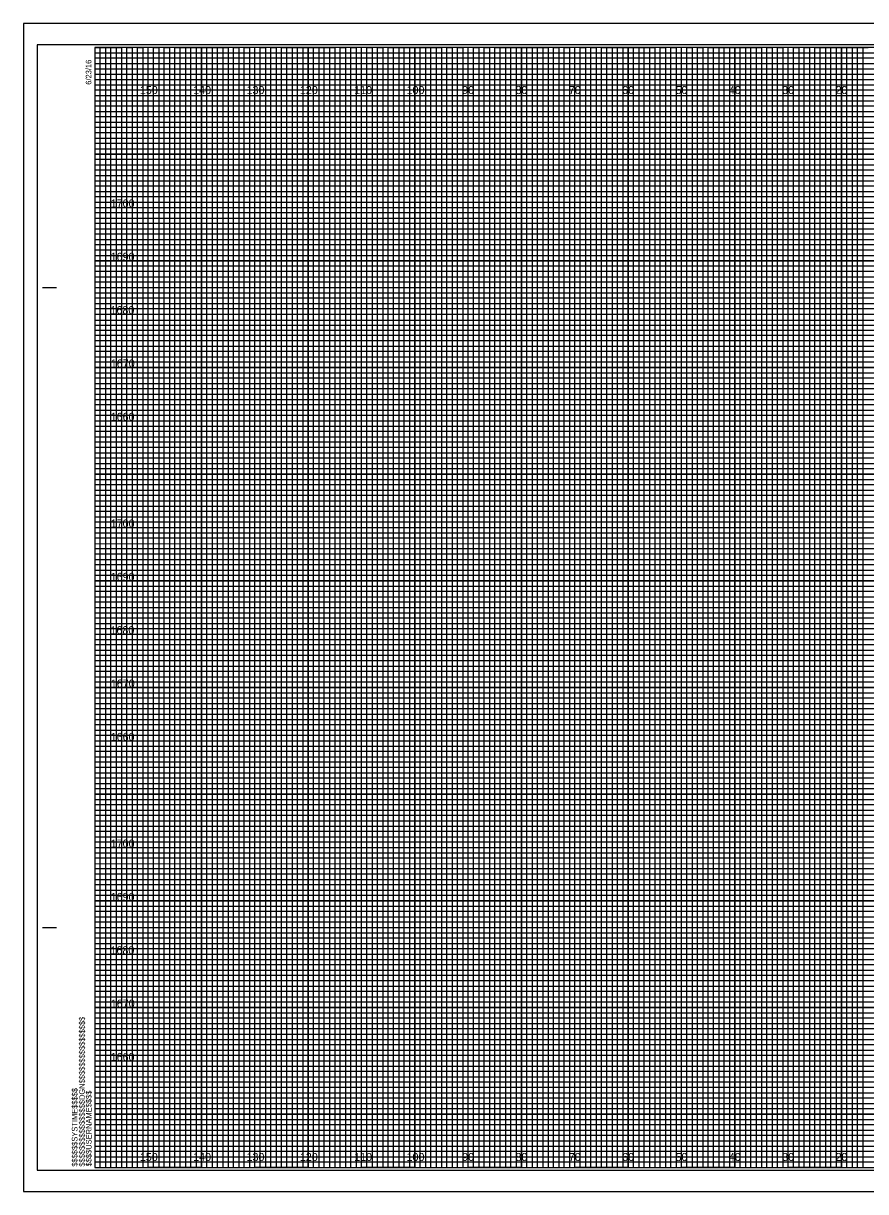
# Model space of a CAD drawing. Extents: x 656 to 993, y -2 to 2857.
# Drawn here: x 656.3 to 814.2, y 1318.3 to 1537.3 of the extents above; entities that cross this region are included whole.
import ezdxf

# ---------------------------------------------------------------- set-up
doc = ezdxf.new("R2010")
doc.units = 0
for name, color, linetype in [('Prop RDY Alternate Text Blue', 7, 'Continuous'), ('Prop Retaining Wall', 7, 'Continuous'), ('Prop SS Cut Line', 7, 'Continuous'), ('Prop SS Fill Line', 7, 'Continuous'), ('Prop SS Transition Line', 7, 'Continuous'), ('Raster_Level_0', 7, 'Continuous'), ('Raster_Level_3', 7, 'Continuous'), ('Scratch_Level_3', 7, 'Continuous'), ('Scratch_Level_7', 7, 'Continuous'), ('Typical Guardrail CELL', 7, 'Continuous'), ('Typical Text Asphalt at Bridge Approach CELL', 7, 'Continuous')]:
    doc.layers.add(name, color=color, linetype=linetype)

msp = doc.modelspace()

# ---------------------------------------------------------------- linework, layer by layer
at = {"layer": 'Prop RDY Alternate Text Blue'}
for p, q in [((679.74, 1322.8), (679.74, 1532.8)), ((689.74, 1322.8), (689.74, 1532.8)), ((699.74, 1322.8), (699.74, 1532.8)), ((709.74, 1322.8), (709.74, 1532.8)), ((719.74, 1322.8), (719.74, 1532.8)), ((729.74, 1322.8), (729.74, 1532.8)), ((739.74, 1322.8), (739.74, 1532.8)), ((749.74, 1322.8), (749.74, 1532.8)), ((759.74, 1322.8), (759.74, 1532.8)), ((769.74, 1322.8), (769.74, 1532.8)), ((779.74, 1322.8), (779.74, 1532.8)), ((789.74, 1322.8), (789.74, 1532.8)), ((799.74, 1322.8), (799.74, 1532.8)), ((809.74, 1322.8), (809.74, 1532.8)), ((669.74, 1522.8), (989.74, 1522.8)), ((669.74, 1512.8), (989.74, 1512.8)), ((669.74, 1502.8), (989.74, 1502.8)), ((669.74, 1492.8), (989.74, 1492.8)), ((669.74, 1482.8), (989.74, 1482.8)), ((669.74, 1472.8), (989.74, 1472.8)), ((669.74, 1462.8), (989.74, 1462.8)), ((669.74, 1452.8), (989.74, 1452.8)), ((669.74, 1442.8), (989.74, 1442.8)), ((669.74, 1432.8), (989.74, 1432.8)), ((669.74, 1422.8), (989.74, 1422.8)), ((669.74, 1412.8), (989.74, 1412.8)), ((669.74, 1402.8), (989.74, 1402.8)), ((669.74, 1392.8), (989.74, 1392.8)), ((669.74, 1382.8), (989.74, 1382.8)), ((669.74, 1372.8), (989.74, 1372.8)), ((669.74, 1362.8), (989.74, 1362.8)), ((669.74, 1352.8), (989.74, 1352.8)), ((669.74, 1342.8), (989.74, 1342.8)), ((669.74, 1332.8), (989.74, 1332.8))]:
    msp.add_line(p, q, dxfattribs=at)
at = {"layer": 'Prop Retaining Wall'}
for p, q in [((659.94, 1487.8), (662.44, 1487.8)), ((660.04, 1487.8), (662.54, 1487.8)), ((659.94, 1367.8), (662.44, 1367.8)), ((660.04, 1367.8), (662.54, 1367.8)), ((669.74, 1322.8), (669.74, 1322.8)), ((669.74, 1322.8), (669.74, 1322.8)), ((669.74, 1322.8), (669.74, 1322.8)), ((669.74, 1322.8), (669.74, 1322.8)), ((669.74, 1322.8), (669.74, 1322.8)), ((669.74, 1322.8), (669.74, 1322.8)), ((669.74, 1322.8), (669.74, 1322.8))]:
    msp.add_line(p, q, dxfattribs=at)
msp.add_lwpolyline([(989.74, 1532.8), (669.74, 1532.8), (669.74, 1322.8), (989.74, 1322.8)], close=True, dxfattribs=at)
at = {"layer": 'Prop SS Cut Line'}
for points in [[(669.74, 1532.8), (674.74, 1532.8), (674.74, 1322.8), (684.74, 1322.8), (684.74, 1532.8), (694.74, 1532.8), (694.74, 1322.8), (704.74, 1322.8), (704.74, 1532.8), (714.74, 1532.8), (714.74, 1322.8), (724.74, 1322.8), (724.74, 1532.8), (734.74, 1532.8), (734.74, 1322.8), (744.74, 1322.8), (744.74, 1532.8), (754.74, 1532.8), (754.74, 1322.8), (764.74, 1322.8), (764.74, 1532.8), (774.74, 1532.8), (774.74, 1322.8), (784.74, 1322.8), (784.74, 1532.8), (794.74, 1532.8), (794.74, 1322.8), (804.74, 1322.8), (804.74, 1532.8), (814.74, 1532.8)], [(669.74, 1527.8), (944.74, 1527.8)], [(669.74, 1507.8), (989.74, 1507.8), (989.74, 1517.8), (669.74, 1517.8)], [(669.74, 1487.8), (989.74, 1487.8), (989.74, 1497.8), (669.74, 1497.8)], [(669.74, 1467.8), (989.74, 1467.8), (989.74, 1477.8), (669.74, 1477.8)], [(669.74, 1447.8), (989.74, 1447.8), (989.74, 1457.8), (669.74, 1457.8)], [(669.74, 1427.8), (989.74, 1427.8), (989.74, 1437.8), (669.74, 1437.8)], [(669.74, 1407.8), (989.74, 1407.8), (989.74, 1417.8), (669.74, 1417.8)], [(669.74, 1387.8), (989.74, 1387.8), (989.74, 1397.8), (669.74, 1397.8)], [(669.74, 1367.8), (989.74, 1367.8), (989.74, 1377.8), (669.74, 1377.8)], [(669.74, 1347.8), (989.74, 1347.8), (989.74, 1357.8), (669.74, 1357.8)], [(669.74, 1327.8), (989.74, 1327.8), (989.74, 1337.8), (669.74, 1337.8)]]:
    msp.add_lwpolyline(points, dxfattribs=at)
at = {"layer": 'Prop SS Fill Line'}
for p, q in [((679.74, 1532.8), (669.74, 1532.8)), ((679.74, 1322.8), (679.74, 1532.8)), ((699.74, 1532.8), (689.74, 1532.8)), ((689.74, 1532.8), (689.74, 1322.8)), ((699.74, 1322.8), (699.74, 1532.8)), ((719.74, 1532.8), (709.74, 1532.8)), ((709.74, 1532.8), (709.74, 1322.8)), ((719.74, 1322.8), (719.74, 1532.8)), ((739.74, 1532.8), (729.74, 1532.8)), ((729.74, 1532.8), (729.74, 1322.8)), ((739.74, 1322.8), (739.74, 1532.8)), ((759.74, 1532.8), (749.74, 1532.8)), ((749.74, 1532.8), (749.74, 1322.8)), ((759.74, 1322.8), (759.74, 1532.8)), ((779.74, 1532.8), (769.74, 1532.8)), ((769.74, 1532.8), (769.74, 1322.8)), ((779.74, 1322.8), (779.74, 1532.8)), ((799.74, 1532.8), (789.74, 1532.8)), ((789.74, 1532.8), (789.74, 1322.8)), ((799.74, 1322.8), (799.74, 1532.8)), ((819.74, 1532.8), (809.74, 1532.8)), ((809.74, 1532.8), (809.74, 1322.8)), ((689.74, 1322.8), (679.74, 1322.8)), ((709.74, 1322.8), (699.74, 1322.8)), ((729.74, 1322.8), (719.74, 1322.8)), ((749.74, 1322.8), (739.74, 1322.8)), ((769.74, 1322.8), (759.74, 1322.8)), ((789.74, 1322.8), (779.74, 1322.8)), ((809.74, 1322.8), (799.74, 1322.8))]:
    msp.add_line(p, q, dxfattribs=at)
for points in [[(669.74, 1522.8), (989.74, 1522.8), (989.74, 1512.8), (669.74, 1512.8)], [(669.74, 1502.8), (989.74, 1502.8), (989.74, 1492.8), (669.74, 1492.8)], [(669.74, 1482.8), (989.74, 1482.8), (989.74, 1472.8), (669.74, 1472.8)], [(669.74, 1462.8), (989.74, 1462.8), (989.74, 1452.8), (669.74, 1452.8)], [(669.74, 1442.8), (989.74, 1442.8), (989.74, 1432.8), (669.74, 1432.8)], [(669.74, 1422.8), (989.74, 1422.8), (989.74, 1412.8), (669.74, 1412.8)], [(669.74, 1402.8), (989.74, 1402.8), (989.74, 1392.8), (669.74, 1392.8)], [(669.74, 1382.8), (989.74, 1382.8), (989.74, 1372.8), (669.74, 1372.8)], [(669.74, 1362.8), (989.74, 1362.8), (989.74, 1352.8), (669.74, 1352.8)], [(669.74, 1342.8), (989.74, 1342.8), (989.74, 1332.8), (669.74, 1332.8)]]:
    msp.add_lwpolyline(points, dxfattribs=at)
at = {"layer": 'Prop SS Transition Line'}
for p, q in [((669.74, 1531.8), (929.74, 1531.8)), ((929.74, 1530.78), (669.74, 1530.78)), ((669.74, 1530.78), (669.74, 1529.8)), ((669.74, 1529.8), (929.74, 1529.8)), ((929.74, 1528.69), (669.74, 1528.69)), ((669.74, 1528.69), (669.74, 1526.8)), ((669.74, 1526.8), (989.74, 1526.8))]:
    msp.add_line(p, q, dxfattribs=at)
for points in [[(669.74, 1525.8), (939.74, 1525.8), (989.74, 1525.8), (989.74, 1524.8), (669.74, 1524.8)], [(669.74, 1523.8), (989.74, 1523.8), (989.74, 1521.8), (669.74, 1521.8)], [(669.74, 1520.8), (989.74, 1520.8), (989.74, 1519.8), (669.74, 1519.78)], [(669.74, 1518.8), (989.74, 1518.8), (989.74, 1516.8), (669.74, 1516.8)], [(669.74, 1515.8), (989.74, 1515.8), (989.74, 1514.8), (669.74, 1514.8)], [(669.74, 1513.8), (989.74, 1513.8), (989.74, 1511.8), (669.74, 1511.8)], [(669.74, 1510.8), (989.74, 1510.8), (989.74, 1509.8), (669.74, 1509.8)], [(669.74, 1508.8), (989.74, 1508.8), (989.74, 1506.8), (669.74, 1506.8)], [(669.74, 1505.8), (989.74, 1505.8), (989.74, 1504.8), (669.74, 1504.8)], [(669.74, 1503.8), (989.74, 1503.8), (989.74, 1501.8), (669.74, 1501.8)], [(669.74, 1500.8), (989.74, 1500.8), (989.74, 1499.8), (669.74, 1499.8)], [(669.74, 1498.8), (989.74, 1498.8), (989.74, 1496.75), (989.74, 1495.8), (989.74, 1494.8), (669.74, 1494.8)], [(669.74, 1496.8), (989.74, 1496.8), (989.74, 1495.8), (669.74, 1495.8)], [(669.74, 1493.8), (989.74, 1493.8), (989.74, 1491.8), (669.74, 1491.83)], [(669.74, 1491.83), (989.74, 1491.8), (989.74, 1490.8), (669.74, 1490.8)], [(669.74, 1489.8), (989.74, 1489.8), (989.74, 1488.8), (669.74, 1488.8)], [(669.74, 1486.8), (989.74, 1486.8), (989.74, 1485.8), (669.74, 1485.8)], [(669.74, 1484.8), (989.74, 1484.8), (989.74, 1483.8), (669.74, 1483.8)], [(669.67, 1481.69), (989.74, 1481.69), (989.74, 1480.68), (669.67, 1480.68)], [(669.74, 1479.8), (989.74, 1479.8), (989.74, 1478.8), (669.74, 1478.8)], [(669.74, 1476.8), (989.74, 1476.8), (989.74, 1475.8), (669.74, 1475.8)], [(669.74, 1474.8), (989.74, 1474.8), (989.74, 1473.8), (669.74, 1473.8)], [(669.74, 1471.8), (989.74, 1471.8), (989.74, 1470.8), (669.74, 1470.8)], [(669.74, 1469.8), (989.74, 1469.8), (989.74, 1468.8), (669.74, 1468.8)], [(669.74, 1466.8), (989.74, 1466.8), (989.74, 1465.8), (669.74, 1465.8)], [(669.74, 1464.8), (989.74, 1464.8), (989.74, 1463.8), (669.74, 1463.8)], [(669.74, 1461.8), (989.74, 1461.8), (989.73, 1460.78), (669.74, 1460.8)], [(669.74, 1459.8), (989.74, 1459.8), (989.74, 1458.8), (669.74, 1458.8)], [(669.74, 1456.8), (989.74, 1456.8), (989.74, 1455.8), (669.74, 1455.8)], [(669.74, 1454.8), (989.74, 1454.8), (989.74, 1453.8), (669.74, 1453.8)], [(669.74, 1451.8), (989.74, 1451.8), (989.74, 1450.8), (669.74, 1450.8)], [(669.74, 1449.8), (989.74, 1449.8), (989.74, 1448.8), (669.74, 1448.8)], [(669.74, 1446.8), (989.74, 1446.8), (989.74, 1445.8), (669.74, 1445.8)], [(669.74, 1444.8), (989.74, 1444.8), (989.74, 1443.8), (669.74, 1443.8)], [(669.74, 1441.8), (989.74, 1441.8), (989.74, 1440.8), (669.74, 1440.8)], [(669.74, 1439.79), (989.81, 1439.71), (989.74, 1438.8), (669.74, 1438.8)], [(669.74, 1436.8), (989.74, 1436.8), (989.74, 1435.8), (669.74, 1435.8)], [(669.74, 1434.8), (989.74, 1434.8), (989.74, 1433.8), (669.74, 1433.8)], [(669.74, 1431.8), (989.74, 1431.8), (989.74, 1430.8), (669.74, 1430.8)], [(669.74, 1429.8), (989.74, 1429.8), (989.74, 1428.8), (669.74, 1428.8)], [(669.74, 1426.8), (989.74, 1426.8), (989.74, 1425.8), (669.74, 1425.8)], [(669.74, 1424.8), (989.74, 1424.8), (989.74, 1423.8), (669.74, 1423.8)], [(669.74, 1421.8), (989.74, 1421.8), (989.74, 1420.8), (669.74, 1420.8)], [(669.74, 1419.8), (989.74, 1419.8), (989.74, 1418.8), (669.74, 1418.8)], [(669.74, 1416.8), (989.74, 1416.8), (989.74, 1415.8), (669.74, 1415.8)], [(669.74, 1414.8), (989.74, 1414.8), (989.74, 1413.8), (669.74, 1413.8)], [(669.74, 1411.8), (989.74, 1411.8), (989.74, 1410.8), (669.74, 1410.8)], [(669.74, 1409.8), (989.74, 1409.8), (989.74, 1408.8), (669.74, 1408.8)], [(669.74, 1406.8), (989.74, 1406.8), (989.74, 1405.8), (669.74, 1405.8)], [(669.74, 1404.8), (989.74, 1404.8), (989.74, 1403.8), (669.74, 1403.8)], [(669.74, 1401.8), (989.74, 1401.8), (989.73, 1400.78), (669.74, 1400.8)], [(669.74, 1399.8), (989.74, 1399.8), (989.74, 1398.8), (669.74, 1398.8)], [(669.74, 1396.8), (989.74, 1396.8), (989.74, 1395.8), (669.74, 1395.8)], [(669.74, 1394.8), (989.74, 1394.8), (989.74, 1393.8), (669.74, 1393.8)], [(669.74, 1391.8), (989.74, 1391.8), (989.74, 1390.8), (669.74, 1390.8)], [(669.74, 1389.8), (989.74, 1389.8), (989.74, 1388.8), (669.74, 1388.8)], [(669.74, 1386.8), (989.74, 1386.8), (989.74, 1385.8), (669.74, 1385.8)], [(669.74, 1384.8), (989.74, 1384.8), (989.74, 1383.8), (669.74, 1383.8)], [(669.74, 1381.8), (989.74, 1381.8), (989.74, 1380.8), (669.74, 1380.8)], [(669.74, 1379.79), (989.81, 1379.71), (989.74, 1378.8), (669.74, 1378.8)], [(669.74, 1376.8), (989.74, 1376.8), (989.74, 1375.8), (669.74, 1375.8)], [(669.74, 1374.8), (989.74, 1374.8), (989.74, 1373.8), (669.74, 1373.8)], [(669.74, 1371.8), (989.74, 1371.8), (989.74, 1370.8), (669.74, 1370.8)], [(669.74, 1369.8), (989.74, 1369.8), (989.74, 1368.8), (669.74, 1368.8)], [(669.74, 1366.8), (989.74, 1366.8), (989.74, 1365.8), (669.74, 1365.8)], [(669.74, 1364.8), (989.74, 1364.8), (989.74, 1363.8), (669.74, 1363.8)], [(669.74, 1361.8), (989.74, 1361.8), (989.74, 1360.8), (669.74, 1360.8)], [(669.74, 1359.8), (989.74, 1359.8), (989.74, 1358.8), (669.74, 1358.8)], [(669.74, 1356.8), (989.74, 1356.8), (989.74, 1355.8), (669.74, 1355.8)], [(669.74, 1354.8), (989.74, 1354.8), (989.74, 1353.8), (669.74, 1353.8)], [(669.74, 1351.8), (989.74, 1351.8), (989.74, 1350.8), (669.74, 1350.8)], [(669.74, 1349.8), (989.74, 1349.8), (989.74, 1348.8), (669.74, 1348.8)], [(669.74, 1346.8), (989.74, 1346.8), (989.74, 1345.8), (669.74, 1345.8)], [(669.74, 1344.8), (989.74, 1344.8), (989.74, 1343.8), (669.74, 1343.8)], [(669.74, 1341.8), (989.74, 1341.8), (989.74, 1340.8), (669.74, 1340.8)], [(669.74, 1339.8), (989.74, 1339.8), (989.74, 1338.8), (669.74, 1338.8)], [(669.74, 1336.8), (989.74, 1336.8), (989.74, 1335.8), (669.74, 1335.8)], [(669.74, 1334.8), (989.74, 1334.8), (989.74, 1333.8), (669.74, 1333.8)], [(669.74, 1331.8), (989.74, 1331.8), (989.74, 1330.8), (669.74, 1330.8)], [(669.74, 1329.8), (989.74, 1329.8), (989.74, 1328.8), (669.74, 1328.8)], [(669.74, 1326.8), (989.74, 1326.8), (989.74, 1325.8), (669.74, 1325.8)], [(669.74, 1324.8), (989.74, 1324.8), (989.74, 1323.8), (669.74, 1323.8)]]:
    msp.add_lwpolyline(points, dxfattribs=at)
at = {"layer": 'Raster_Level_3'}
for points in [[(669.74, 1322.8), (670.74, 1322.8), (670.74, 1532.8), (671.74, 1532.8), (671.74, 1322.8)], [(671.74, 1322.8), (672.74, 1322.8), (672.74, 1532.8), (673.74, 1532.8), (673.74, 1322.8)], [(674.74, 1322.8), (675.74, 1322.8), (675.74, 1532.8), (676.74, 1532.8), (676.74, 1322.8)], [(676.74, 1322.8), (677.74, 1322.8), (677.74, 1532.8), (678.74, 1532.8), (678.74, 1322.8)], [(679.74, 1322.8), (680.74, 1322.8), (680.74, 1532.8), (681.74, 1532.8), (681.74, 1322.8)], [(681.74, 1322.8), (682.74, 1322.8), (682.74, 1532.8), (683.74, 1532.8), (683.74, 1322.8)], [(684.74, 1322.8), (685.74, 1322.8), (685.74, 1532.8), (686.74, 1532.8), (686.74, 1322.8)], [(686.74, 1322.8), (687.74, 1322.8), (687.74, 1532.8), (688.74, 1532.8), (688.74, 1322.8)], [(689.74, 1322.8), (690.74, 1322.8), (690.74, 1532.8), (691.74, 1532.8), (691.74, 1322.8)], [(691.74, 1322.8), (692.74, 1322.8), (692.74, 1532.8), (693.74, 1532.8), (693.74, 1322.8)], [(694.74, 1322.8), (695.74, 1322.8), (695.74, 1532.8), (696.74, 1532.8), (696.74, 1322.8)], [(696.74, 1322.8), (697.74, 1322.8), (697.74, 1532.8), (698.74, 1532.8), (698.74, 1322.8)], [(699.74, 1322.8), (700.74, 1322.8), (700.74, 1532.8), (701.74, 1532.8), (701.74, 1322.8)], [(701.74, 1322.8), (702.74, 1322.8), (702.74, 1532.8), (703.74, 1532.8), (703.74, 1322.8)], [(704.74, 1322.8), (705.74, 1322.8), (705.74, 1532.8), (706.74, 1532.8), (706.74, 1322.8)], [(706.74, 1322.8), (707.74, 1322.8), (707.74, 1532.8), (708.74, 1532.8), (708.74, 1322.8)], [(709.74, 1322.8), (710.74, 1322.8), (710.74, 1532.8), (711.74, 1532.8), (711.74, 1322.8)], [(711.74, 1322.8), (712.74, 1322.8), (712.74, 1532.8), (713.74, 1532.8), (713.74, 1322.8)], [(714.74, 1322.8), (715.74, 1322.8), (715.74, 1532.8), (716.74, 1532.8), (716.74, 1322.8)], [(716.74, 1322.8), (717.74, 1322.8), (717.74, 1532.8), (718.74, 1532.8), (718.74, 1322.8)], [(719.74, 1322.8), (720.74, 1322.8), (720.74, 1532.8), (721.74, 1532.8), (721.74, 1322.8)], [(721.74, 1322.8), (722.74, 1322.8), (722.74, 1532.8), (723.74, 1532.8), (723.74, 1322.8)], [(724.74, 1322.8), (725.74, 1322.8), (725.74, 1532.8), (726.74, 1532.8), (726.74, 1322.8)], [(726.74, 1322.8), (727.74, 1322.8), (727.74, 1532.8), (728.74, 1532.8), (728.74, 1322.8)], [(729.74, 1322.8), (730.74, 1322.8), (730.74, 1532.8), (731.74, 1532.8), (731.74, 1322.8)], [(731.74, 1322.8), (732.74, 1322.8), (732.74, 1532.8), (733.74, 1532.8), (733.74, 1322.8)], [(734.74, 1322.8), (735.74, 1322.8), (735.74, 1532.8), (736.74, 1532.8), (736.74, 1322.8)], [(736.74, 1322.8), (737.74, 1322.8), (737.74, 1532.8), (738.74, 1532.8), (738.74, 1322.8)], [(739.74, 1322.8), (740.74, 1322.8), (740.74, 1532.8), (741.74, 1532.8), (741.74, 1322.8)], [(741.74, 1322.8), (742.74, 1322.8), (742.74, 1532.8), (743.74, 1532.8), (743.74, 1322.8)], [(744.74, 1322.8), (745.74, 1322.8), (745.74, 1532.8), (746.74, 1532.8), (746.74, 1322.8)], [(746.74, 1322.8), (747.74, 1322.8), (747.74, 1532.8), (748.74, 1532.8), (748.74, 1322.8)], [(749.74, 1322.8), (750.74, 1322.8), (750.74, 1532.8), (751.74, 1532.8), (751.74, 1322.8)], [(751.74, 1322.8), (752.74, 1322.8), (752.74, 1532.8), (753.74, 1532.8), (753.74, 1322.8)], [(754.74, 1322.8), (755.74, 1322.8), (755.74, 1532.8), (756.74, 1532.8), (756.74, 1322.8)], [(756.74, 1322.8), (757.74, 1322.8), (757.74, 1532.8), (758.74, 1532.8), (758.74, 1322.8)], [(759.74, 1322.8), (760.74, 1322.8), (760.74, 1532.8), (761.74, 1532.8), (761.74, 1322.8)], [(761.74, 1322.8), (762.74, 1322.8), (762.74, 1532.8), (763.74, 1532.8), (763.74, 1322.8)], [(764.74, 1322.8), (765.74, 1322.8), (765.74, 1532.8), (766.74, 1532.8), (766.74, 1322.8)], [(766.74, 1322.8), (767.74, 1322.8), (767.74, 1532.8), (768.74, 1532.8), (768.74, 1322.8)], [(769.74, 1322.8), (770.74, 1322.8), (770.74, 1532.8), (771.74, 1532.8), (771.74, 1322.8)], [(771.74, 1322.8), (772.74, 1322.8), (772.74, 1532.8), (773.74, 1532.8), (773.74, 1322.8)], [(774.74, 1322.8), (775.74, 1322.8), (775.74, 1532.8), (776.74, 1532.8), (776.74, 1322.8)], [(776.74, 1322.8), (777.74, 1322.8), (777.74, 1532.8), (778.74, 1532.8), (778.74, 1322.8)], [(779.74, 1322.8), (780.74, 1322.8), (780.74, 1532.8), (781.74, 1532.8), (781.74, 1322.8)], [(781.74, 1322.8), (782.74, 1322.8), (782.74, 1532.8), (783.74, 1532.8), (783.74, 1322.8)], [(784.74, 1322.8), (785.74, 1322.8), (785.74, 1532.8), (786.74, 1532.8), (786.74, 1322.8)], [(786.74, 1322.8), (787.74, 1322.8), (787.74, 1532.8), (788.74, 1532.8), (788.74, 1322.8)], [(789.74, 1322.8), (790.74, 1322.8), (790.74, 1532.8), (791.74, 1532.8), (791.74, 1322.8)], [(791.74, 1322.8), (792.74, 1322.8), (792.74, 1532.8), (793.74, 1532.8), (793.74, 1322.8)], [(794.74, 1322.8), (795.74, 1322.8), (795.74, 1532.8), (796.74, 1532.8), (796.74, 1322.8)], [(796.74, 1322.8), (797.74, 1322.8), (797.74, 1532.8), (798.74, 1532.8), (798.74, 1322.8)], [(799.74, 1322.8), (800.74, 1322.8), (800.74, 1532.8), (801.74, 1532.8), (801.74, 1322.8)], [(801.74, 1322.8), (802.74, 1322.8), (802.74, 1532.8), (803.74, 1532.8), (803.74, 1322.8)], [(804.74, 1322.8), (805.74, 1322.8), (805.74, 1532.8), (806.74, 1532.8), (806.74, 1322.8)], [(806.74, 1322.8), (807.74, 1322.8), (807.74, 1532.8), (808.74, 1532.8), (808.74, 1322.8)], [(809.74, 1322.8), (810.74, 1322.8), (810.74, 1532.8), (811.74, 1532.8), (811.74, 1322.8)], [(811.74, 1322.8), (812.74, 1322.8), (812.74, 1532.8), (813.74, 1532.8), (813.74, 1322.8)]]:
    msp.add_lwpolyline(points, dxfattribs=at)
at = {"layer": 'Scratch_Level_7'}
msp.add_lwpolyline([(656.34, 1318.3), (993.04, 1318.3), (993.04, 1537.3), (656.34, 1537.3)], close=True, dxfattribs=at)
at = {"layer": 'Typical Guardrail CELL'}
msp.add_lwpolyline([(658.94, 1322.3), (992.14, 1322.3), (992.14, 1533.3), (658.94, 1533.3)], close=True, dxfattribs=at)
at = {"layer": 'Typical Text Asphalt at Bridge Approach CELL'}
for p, q in [((993.04, 1537.3), (656.34, 1537.3)), ((656.34, 1537.3), (656.34, 1318.3)), ((656.34, 1318.3), (993.04, 1318.3))]:
    msp.add_line(p, q, dxfattribs=at)

# ---------------------------------------------------------------- texts
at = {"layer": 'Prop Retaining Wall'}
for s, p in [('6/23/16', (669.09, 1525.8)), ('$$$$$$$$$$$$$$$$DGN$$$$$$$$$$$$$$$$', (667.86, 1322.98)), ('$$$$$$SYSTIME$$$$$', (666.48, 1322.98)), ('$$$$USERNAME$$$$', (669.12, 1323.03))]:
    msp.add_text(s, height=1.05, rotation=90, dxfattribs=at).set_placement(p)
at = {"layer": 'Raster_Level_0'}
for s, p in [('150', (678.18, 1524.05)), ('140', (688.18, 1524.05)), ('130', (698.18, 1524.05)), ('120', (708.18, 1524.05)), ('110', (718.36, 1524.05)), ('100', (728.18, 1524.05)), ('90', (738.6, 1524.05)), ('80', (748.6, 1524.05)), ('70', (758.6, 1524.05)), ('60', (768.6, 1524.05)), ('50', (778.6, 1524.05)), ('40', (788.6, 1524.05)), ('30', (798.6, 1524.05)), ('20', (808.6, 1524.05)), ('150', (678.18, 1324.05)), ('140', (688.18, 1324.05)), ('130', (698.18, 1324.05)), ('120', (708.18, 1324.05)), ('110', (718.36, 1324.05)), ('100', (728.18, 1324.05)), ('90', (738.6, 1324.05)), ('80', (748.6, 1324.05)), ('70', (758.6, 1324.05)), ('60', (768.6, 1324.05)), ('50', (778.6, 1324.05)), ('40', (788.6, 1324.05)), ('30', (798.6, 1324.05)), ('20', (808.6, 1324.05))]:
    msp.add_text(s, height=1.5, dxfattribs=at).set_placement(p)
at = {"layer": 'Scratch_Level_3'}
for s, p in [('1700', (672.72, 1502.8)), ('1690', (672.71, 1492.8)), ('1680', (672.68, 1482.8)), ('1670', (672.74, 1472.8)), ('1660', (672.71, 1462.8)), ('1700', (672.72, 1442.8)), ('1690', (672.71, 1432.8)), ('1680', (672.68, 1422.8)), ('1670', (672.74, 1412.8)), ('1660', (672.71, 1402.8)), ('1700', (672.72, 1382.8)), ('1690', (672.71, 1372.8)), ('1680', (672.68, 1362.8)), ('1670', (672.74, 1352.8)), ('1660', (672.71, 1342.8))]:
    msp.add_text(s, height=1.5, dxfattribs=at).set_placement(p)

doc.saveas('drawing.dxf')
